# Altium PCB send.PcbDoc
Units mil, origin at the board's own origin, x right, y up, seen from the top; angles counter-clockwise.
Board outline 1102.36 x 1608 mil, 2 copper layers (Top Layer, Bottom Layer); 45 components, 38 nets, 165 pads, 231 vias.
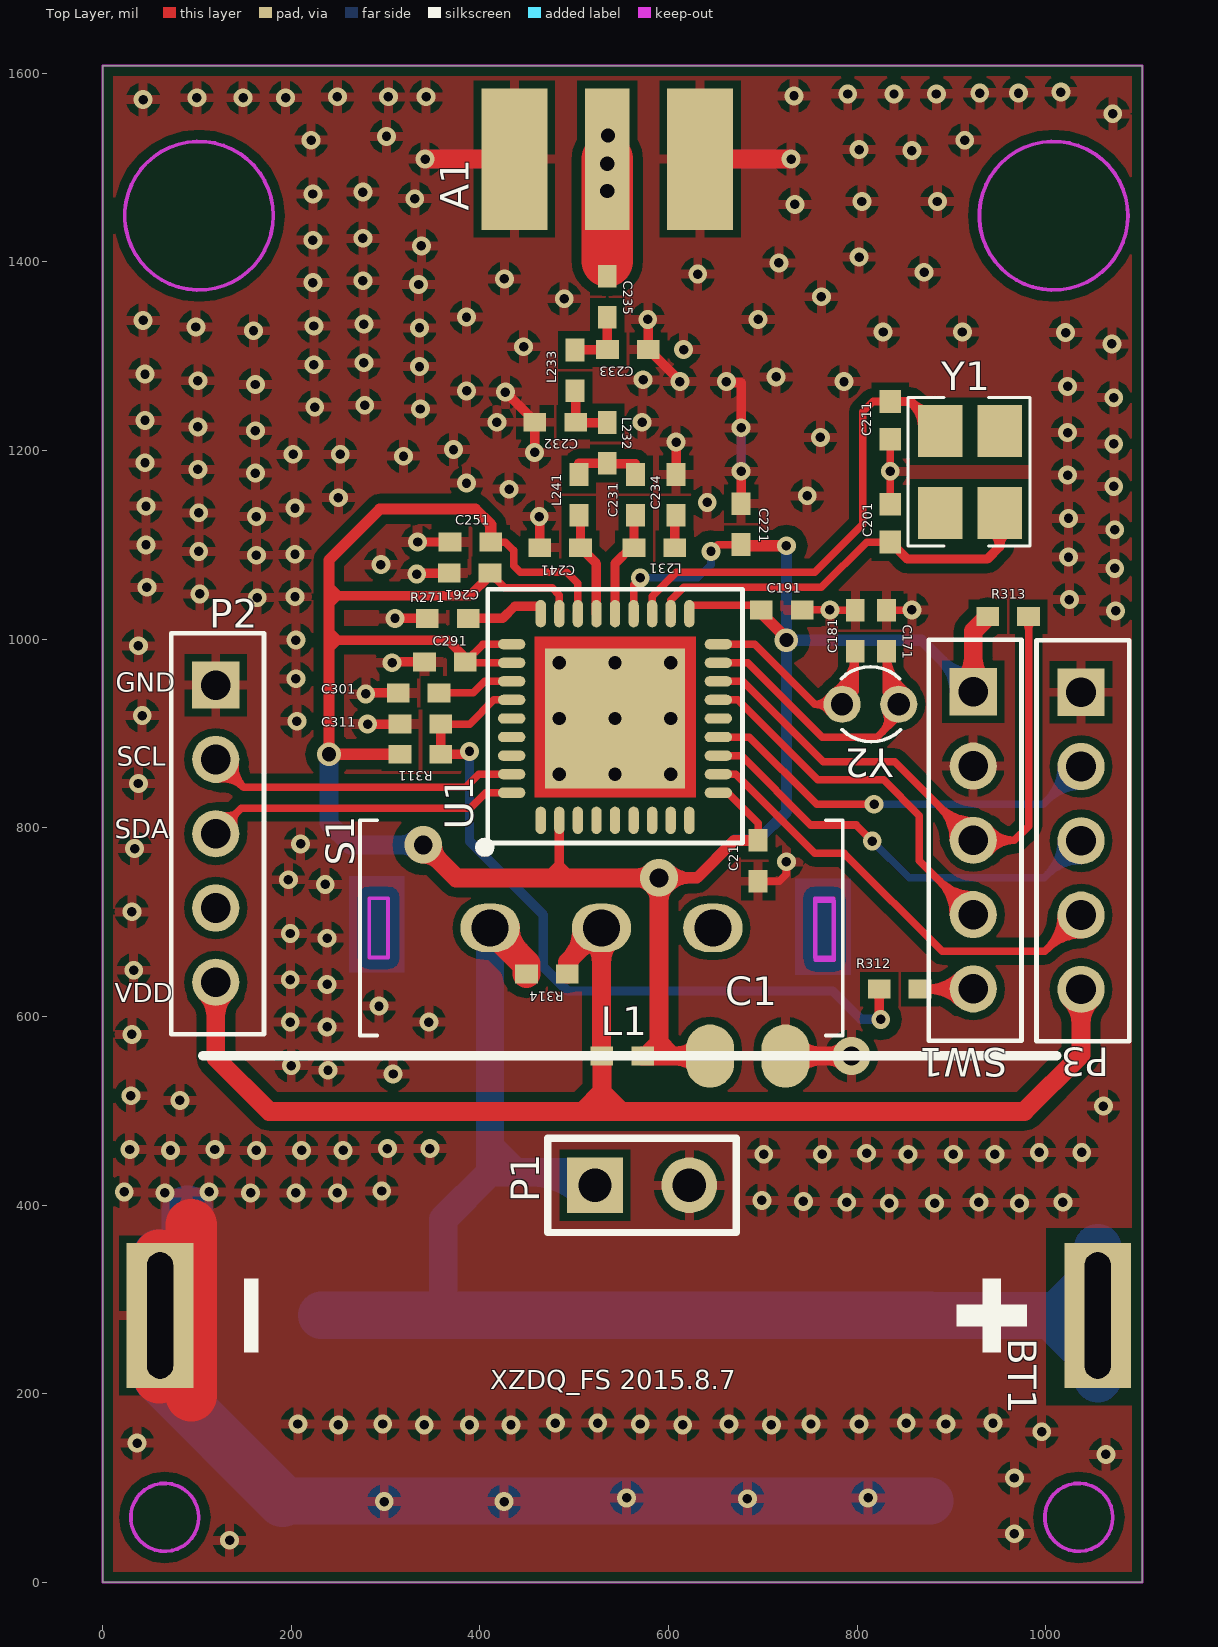
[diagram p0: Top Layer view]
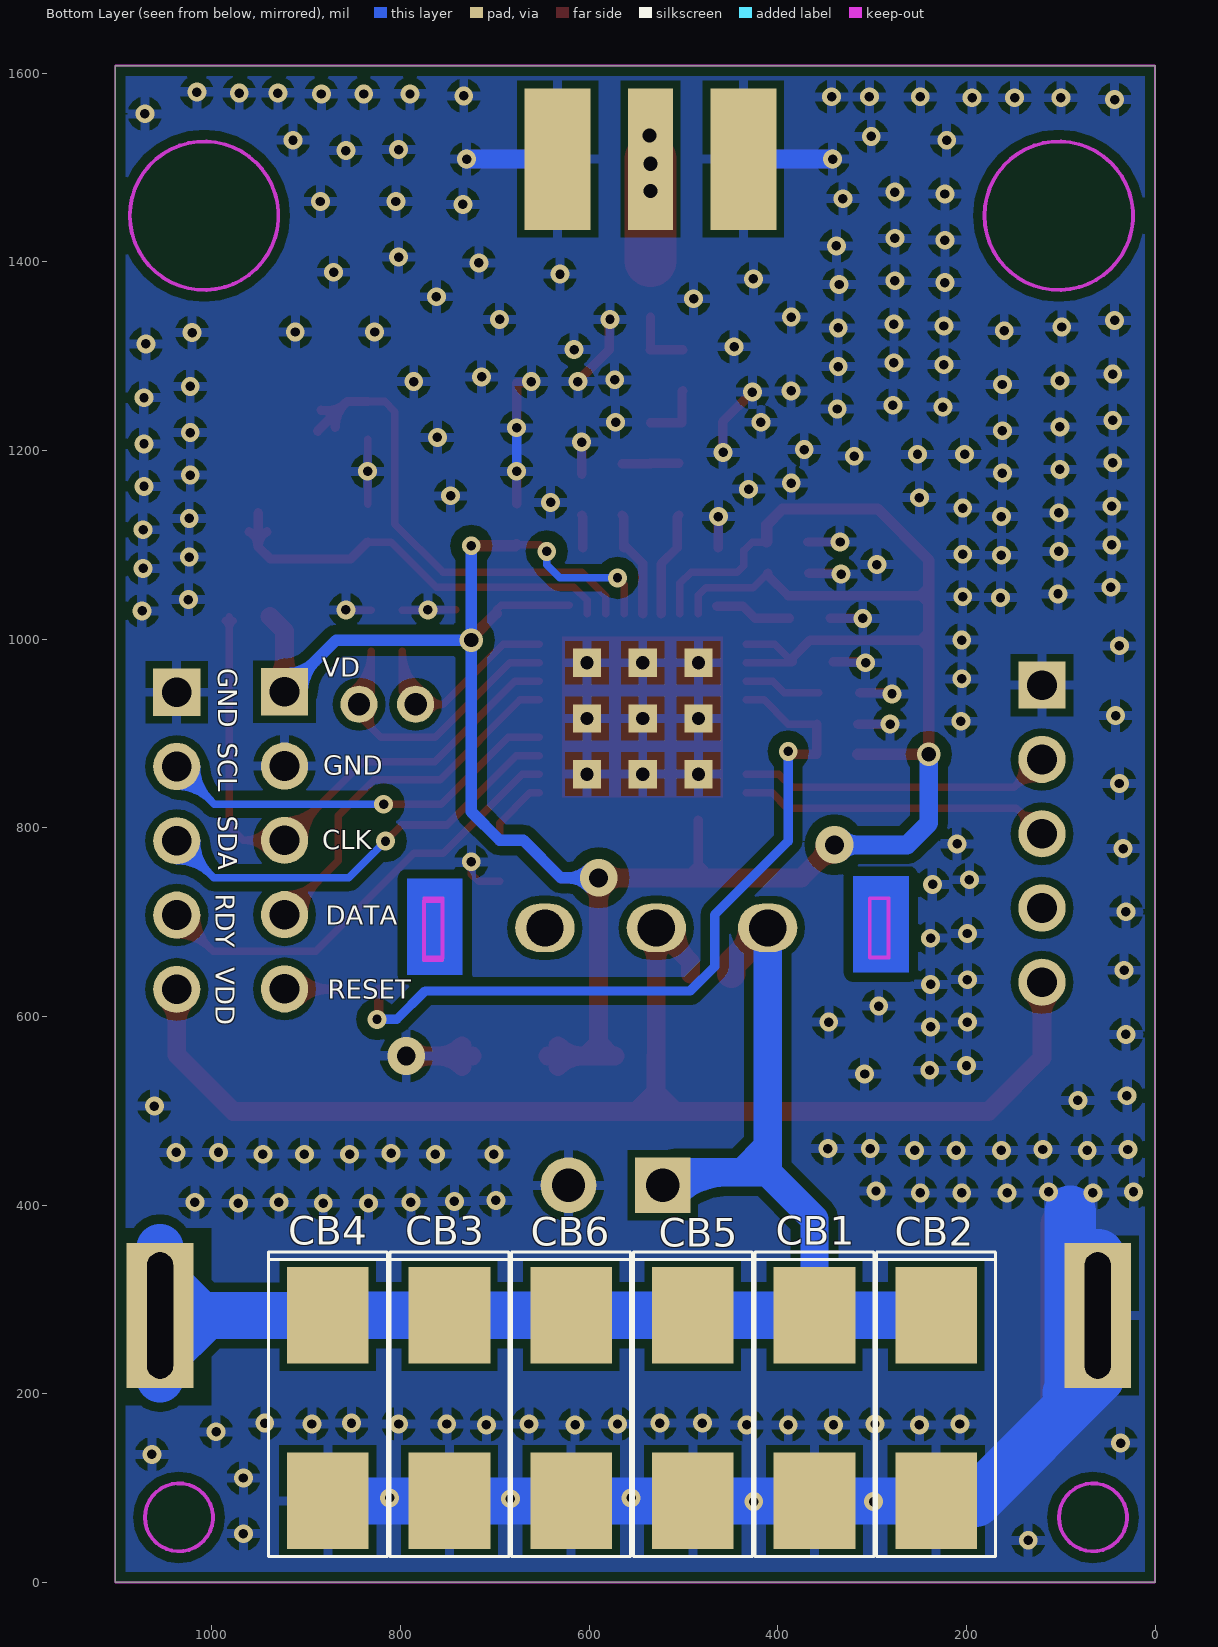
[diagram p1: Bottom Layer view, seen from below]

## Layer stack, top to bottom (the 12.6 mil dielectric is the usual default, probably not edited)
Top Layer: signal copper 1.4
Dielectric: dielectric 12.6, FR-4, Dk 4.8
Bottom Layer: signal copper 1.4

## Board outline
0,0 0,1608 1102.36,1608 1102.36,0

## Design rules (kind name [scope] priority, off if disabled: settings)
Clearance FILLTOPAD [ISFILL vs ISPAD] p1: gap=9
Clearance InPolygon_GND [InNamedPolygon('GND') vs InNet('GND')] p2: gap=8
Clearance InPolygon_GND_P2 [InNamedPolygon('GND_P2') vs InNet('GND')] p3: gap=8
Clearance "InPolygon_GND layer1" [InNamedPolygon('GND layer1') vs InNet('GND')] p4: gap=8
Clearance InPolygon_GND_P1 [InNamedPolygon('GND_P1') vs InNet('GND')] p5: gap=8
Clearance CopperToBoard [InPolygon vs (IsTrack Or IsArc) And OnLayer('Keep-out Layer')] p6: gap=10
Clearance ViaToCopper [IsVia vs InPolygon] p7: gap=12
Clearance ViaToVia [IsVia vs IsVia] p8: gap=8
Clearance PadToCopper [IsPad vs InPolygon] p9: gap=8
Clearance PadToVia [ISPad vs IsVia] p10: gap=8
Clearance PadToPad [IsPad vs IsPad] p11: gap=8
Clearance RouteToPad_1 [IsTrack or IsArc vs IsVia] p12: gap=8
Clearance RouteToPad [IsTrack Or IsArc vs IsPad] p13: gap=8
Clearance RouteToRoute [IsTrack or IsArc vs IsTrack or IsArc] p14: gap=8
Clearance [All] p15: gap=10
ComponentClearance [All] p1: gap=0 collisioncheckmode=3 verticalgap=0 showdistances=FALSE
HoleSize [All] p1: absolutevalues=TRUE maxlimit=1000 minlimit=1 maxpercent=80.000 minpercent=20.000
MinimumSolderMaskSliver [All] p1: minsoldermaskwidth=0
PolygonConnect [All] p1: connectstyle=Relief reliefconductorwidth=10 reliefentries=4 polygonreliefangle="90 Angle"
RoutingVias [All] p1: holewidth=28 width=50 viastyle="Through Hole" minholewidth=10 minwidth=20 maxholewidth=28 maxwidth=50
SilkToSilkClearance [All] p1: silktosilkclearance=0
SilkscreenOverComponentPads [All] p1: minsilkscreentomaskgap=0
SolderMaskExpansion [All] p1: expansion=4
Width [All] p1: maxlimit=60 minlimit=8 preferedwidth=10
23 further rules are at their usual default settings.

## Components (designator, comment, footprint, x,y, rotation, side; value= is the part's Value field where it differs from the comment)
A1 "Antenna" SMA_AT 533.94,1507.93 r180 top
BT1 "VBAT3.6V" BAT 1054.94,283.93 r180 top
C1 "2U2" "0805 (reflow)" 683.94,556.93 r0 top
C21 "100nF" "0402 (REFLOW)" 694.94,764.93 r270 top
C171 "CAP" "0402 (REFLOW)" 830.94,1008.93 r90 top
C181 "CAP" "0402 (REFLOW)" 797.94,1008.93 r90 top
C191 "220pF" "0402 (REFLOW)" 719.94,1030.93 r0 top
C201 "CAP" "0402 (REFLOW LF)" 833.94,1122.93 r90 top
C211 "CAP" "0402 (REFLOW LF)" 835.94,1231.93 r270 top
C221 "100nF" "0402 (REFLOW)" 676.94,1121.93 r90 top
C231 "3.9pF" "0402 (REFLOW)" 564.94,1152.93 r90 top
C232 "8.2pF" "0402 (REFLOW)" 479.94,1229.93 r180 top
C233 "5.6pF" "0402 (REFLOW)" 556.94,1306.93 r0 top
C234 "220pF" "0402 (REFLOW)" 607.94,1152.93 r90 top
C235 "220pF" "0402 (REFLOW)" 534.94,1362.93 r90 top
C241 "3.9pF" "0402 (REFLOW)" 484.94,1096.93 r180 top
C251 "100nF" "0402 (REFLOW)" 389.94,1102.93 r180 top
C261 "220pF" "0402 (REFLOW)" 388.94,1069.93 r180 top
C291 "100nF" "0402 (REFLOW)" 362.94,975.93 r180 top
C301 "1uF" "0402 (REFLOW)" 334.94,942.93 r0 top
C311 "1nF" "0402 (REFLOW)" 336.94,909.93 r180 top
CB1 "220uF" 6032C 359.06,183.81 r90 bottom
CB2 "220uF" 6032C 230.07,183.81 r90 bottom
CB3 "220uF" 6032C 746.04,183.81 r90 bottom
CB4 "220uF" 6032C 875.03,183.81 r90 bottom
CB5 "220uF" 6032C 488.05,183.81 r90 bottom
CB6 "220uF" 6032C 617.04,183.81 r90 bottom
L1 "BLM15HG102SN1D" "0402 (REFLOW)" 550.94,557.93 r180 top
L231 "27nH" "0402 (REFLOW)" 584.94,1096.93 r0 top
L232 "22nH" "0402 (REFLOW)" 534.94,1207.93 r90 top
L233 "27nH" "0402 (REFLOW)" 500.94,1284.93 r90 top
L241 "27nH" "0402 (REFLOW)" 504.94,1152.93 r90 top
P1 "Header 2" HDR1X2 521.94,420.93 r0 top
P2 "Header 5" HD5 119.94,636.23 r90 top
P3 "Header 5" HD5 1037.25,628.7 r90 top
R271 "56K" "0402 (REFLOW)" 365.94,1021.93 r0 top
R311 "2.7K" "0402 (REFLOW)" 336.94,877.93 r180 top
R312 "2.7K" "0402 (REFLOW)" 844.94,628.93 r0 top
R313 "10K" "0402 (REFLOW)" 959.94,1023.93 r180 top
R314 "0R" "0402 (REFLOW)" 470.94,644.93 r0 top
S1 "SS-12F24" SS-12F24 527.83,693.93 r0 top
SW1 "Header 5" HD5 922.94,629.19 r90 top
U1 "CC1110" QLP36/QFN/CC1110 543.2,916.43 r90 top
Y1 "XY1" "XTAL_SMD_3_2x2_5 (3.2 x 2.5 mm)" 948.93,1134.93 r90 top
Y2 "XTAL" "CJ32.768K 2MM*6MM" 783.94,930.93 r0 top

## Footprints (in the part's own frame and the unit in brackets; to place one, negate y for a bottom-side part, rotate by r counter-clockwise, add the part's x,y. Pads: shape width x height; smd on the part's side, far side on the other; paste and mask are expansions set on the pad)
"0402 (REFLOW LF)" [mil]
  rect 24x23 smd paste+0 mask+6: 1(-20,-1) 2(20,-1)
"0402 (REFLOW)" [mil]
  rect 24x20 smd paste+0 mask+4: 1(-21.65,0) 2(21.65,0)
"0805 (reflow)" [mil]
  oval 51x67 smd paste+0 mask+4: 1(-40,1) 2(40,1)
6032C [mm]
  rect 2.6x2.2 smd: 1(2.525,0.051) 2(-2.475,0.051)
  silkscreen extent -3.97,-1.55 4.23,1.65
BAT [mm]
  rect 1.8x3.9 hole 0.7 slot 3.4 at 90 deg: 1(0,0.025) 2(25.25,0.025)
  silkscreen extent 1.1,-6.97 24.1,1.03
"CJ32.768K 2MM*6MM" [mm]
  round 1 hole 0.6: 1(0,0) 2(1.524,0)
  silkscreen extent -0.03,-1.01 1.57,1.01
HD5 [mm]
  round 1.27 hole 0.8 mask+0.07: 1(0,0) 2(2,0) 3(4,0) 4(6,0)
  rect 1.27x1.27 hole 0.8 mask+0.07: 5(8,0)
  silkscreen extent -1.4,-1.3 9.4,1.2
HDR1X2 [mm] "Connector; Header; 2 Position"
  rect 1.5x1.5 hole 0.9: 1(0,0)
  round 1.5 hole 0.9: 2(2.54,0)
  silkscreen extent -1.27,-1.27 3.81,1.27
QLP36/QFN/CC1110 [mil]
  oval 29x11 smd paste-2 mask+4: 1(-108.5,78.74) 2(-108.5,59.06) 3(-108.5,39.37) 4(-108.5,19.68) 5(-108.5,0) 6(-108.5,-19.69) 7(-108.5,-39.37) 8(-108.5,-59.06) 9(-108.5,-78.74) 19(110.5,-78.74) 20(110.5,-59.06) 21(110.5,-39.37) 22(110.5,-19.69) 23(110.5,0) 24(110.5,19.68) 25(110.5,39.37) 26(110.5,59.06) 27(110.5,78.74)
  oval 11x29 smd paste-2 mask+4: 10(-79.32,-109.5) 11(-59.63,-109.5) 12(-39.94,-109.5) 13(-20.26,-109.5) 14(-0.57,-109.5) 15(19.11,-109.5) 16(38.8,-109.5) 17(58.48,-109.5) 18(78.17,-109.5) 28(78.17,109.5) 29(58.48,109.5) 30(38.8,109.5) 31(19.11,109.5) 32(-0.57,109.5) 33(-20.26,109.5) 34(-39.94,109.5) 35(-59.63,109.5) 36(-79.32,109.5)
  rect 30x30 / inner round 60 / far side rect 30x30 hole 14 paste+0 mask+0: 37(-59.63,59.06) 39(-0.57,59.06) 41(58.48,59.06) 47(-59.63,0) 49(-0.57,0) 51(58.48,0) 57(-59.63,-59.06) 59(-0.57,-59.06) 61(58.48,-59.06)
  rect 30x30 smd mask+0: 38(-30.1,59.06) 40(28.95,59.06) 42(-59.63,29.53) 43(-30.1,29.53) 44(-0.57,29.53) 45(28.95,29.53) 46(58.48,29.53) 48(-30.1,0) 50(28.95,0) 52(-59.63,-29.53) 53(-30.1,-29.53) 54(-0.57,-29.53) 55(28.95,-29.53) 56(58.48,-29.53) 58(-30.1,-59.06) 60(28.95,-59.06)
  silkscreen extent -147,-135 136,148
SMA_AT [mil]
  rect 47.24x150 smd far side: 1(-1,-1)
  rect 47.24x150 smd: 1(-1,-1)
  rect 70x150 smd: 2(-99.43,-1) 3(97.43,-1)
  rect 70x150 smd far side: 4(-99.43,-1) 5(97.43,-1)
SS-12F24 [mm]
  oval 1.6x1.3 hole 1: 1(-2.975,0) 2(0.025,0) 3(3.025,0)
  Bottom Layer region: -6.775,-1.2 -5.275,-1.2 -5.275,1.4 -6.775,1.4
  Bottom Layer region: 5.24,-1.276 6.74,-1.276 6.74,1.324 5.24,1.324
  Keep-Out Layer lines w0.1: -6.225,-0.8 -5.725,-0.8 -5.725,0.8 -6.225,0.8 -6.225,0 -6.225,-0.8 ; 5.775,-0.8 5.775,0 5.775,0.8 6.275,0.8 6.275,-0.8 5.775,-0.8 ; 5.79,-0.876 5.79,-0.076 5.79,0.724 6.29,0.724 6.29,-0.876 5.79,-0.876
  silkscreen extent -6.47,-2.9 6.53,2.9
"XTAL_SMD_3_2x2_5 (3.2 x 2.5 mm)" [mm]
  rect 1.4x1.2 smd paste-0.06 mask+0.05: 1(-0.025,-0.051) 2(2.175,-0.051) 3(2.175,1.549) 4(-0.025,1.549)
  silkscreen extent -0.93,-0.86 3.07,2.41

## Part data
BT1: library part Battery, "Multicell Battery"
C1 C21 C191 C221 C231 C232 C233 C234 C235 C241 C251 C261 C291 C301 C311: library part CAP, "CAP"
CB1 CB2 CB3 CB4 CB5 CB6: library part CAP+
L1 L231 L232 L233 L241: library part Inductor, "Inductor"
P1: "Header, 2-Pin"
P2 P3 SW1: "Header, 5-Pin"
R271 R311 R312 R313 R314: library part RES, "RES"
S1: library part SW-SPDT, "Switch"
U1: "Single chip transceiver"
Y1: "四脚晶振"
Y2: "晶振"

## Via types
v1: diameter 20, hole 10, Top Layer to Bottom Layer, 217 vias
v2: diameter 20, hole 10, Top Layer to Bottom Layer, tented both sides, 5 vias
v3: diameter 30, hole 15, Top Layer to Bottom Layer, 3 vias
v4: diameter 40, hole 20, Top Layer to Bottom Layer, tented both sides, 3 vias
v5: diameter 25, hole 15, Top Layer to Bottom Layer, tented both sides, 2 vias
v6: diameter 20, hole 10, Top Layer to Bottom Layer, tented bottom, 1 vias

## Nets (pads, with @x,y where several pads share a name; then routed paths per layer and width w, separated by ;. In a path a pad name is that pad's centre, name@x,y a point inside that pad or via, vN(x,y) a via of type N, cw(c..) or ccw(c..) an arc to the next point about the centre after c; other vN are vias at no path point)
101: C201.1 U1.20 Y1.1 | length 475.8
  Top Layer w8: U1.20 602.25,1041 616.18,1054.93 761.94,1054.93 809.94,1102.93 C201.1
  Top Layer w10: C201.1 852.94,1084.93 937.94,1084.93 950.93,1097.92 ; Y1.1@941.7,1113.82 cw(c932.63,1097.92) 950.93,1097.92 ; Y1.1 950.93,1097.92 ; Y1.1@960.16,1113.82 ccw(c969.23,1097.92) 950.93,1097.92
276: C211.1 U1.21 Y1.3 | length 547.5
  Top Layer w8: U1.21 582.57,1045.56 607.94,1070.93 754.94,1070.93 805.94,1121.93 805.94,1240.93 816.94,1251.93 C211.1
  Top Layer w10: C211.1 856.55,1251.93 Y1.3 ; 858.52,1249.96 ccw(c877.81,1269.25) Y1.3@883.83,1242.64 ; 858.93,1249.55 cw(c833.86,1224.48) Y1.3@869.31,1224.48
489: C181.1 U1.18 Y2.1 | length 380.2
  Top Layer w8: U1.18 691.27,994.6 754.94,930.93 ; Y2.1@770.81,922.34 ccw(c754.94,911.97) 754.94,930.93 ; Y2.1@770.81,939.51 cw(c754.94,949.89) 754.94,930.93 ; Y2.1@775.07,943.87 ccw(c745.31,987.27) C181.1 797.94,944.93 Y2.1 754.94,930.93 ; Y2.1@779.59,937.27 ccw(c755.72,972.09) 797.94,972.09 ; Y2.1@784.12,930.67 ccw(c766.13,956.9) 797.94,956.9
490: C171.1 U1.17 Y2.2 | length 470.1
  Top Layer w8: U1.17 683.95,974.91 762.94,895.93 820.94,895.93 843.94,918.93 Y2.2 830.94,943.93 C171.1 ccw(c884.93,987.27) Y2.2@853.16,943.61 ; 826.94,901.93 ccw(c814.01,914.86) Y2.2@830.12,923.51 ; 830.94,955.85 ccw(c862.06,955.85) Y2.2@843.75,930.67 ; 830.94,971.56 ccw(c873.5,971.56) Y2.2@848.46,937.14 ; 834.55,909.54 ccw(c823.91,920.18) Y2.2@837.17,927.29
531: C301.2 U1.30 | length 82.2
  Top Layer w8: C301.2 392.94,942.93 405.24,955.23 U1.30
536: R271.2 U1.27 | length 82.7
  Top Layer w10: R271.2 423.94,1021.93 436.94,1034.93 U1.27@464.94,1034.93
561: C1.1 C21.1 C191.1 C221.1 C251.1 C261.1 C291.1 L1.1 R311.2 R313.2 SW1.5 U1.2 U1.10 U1.19 U1.22 U1.25 U1.26 U1.28 U1.29 | length 3865
  Top Layer w8: C261.1 426.08,1054.44 476.43,1054.44 484.14,1046.72 U1.26 ; C251.1 426.94,1102.93 435.94,1093.93 435.94,1077.93 442.94,1070.93 491.94,1070.93 503.83,1059.04 U1.25 ; U1.29 385.61,974.91 C291.1 403.26,994.6 U1.28 ; U1.22 562.88,1057.87 v1(569.94,1064.93) ; U1.19@620.94,1035.93 693.28,1035.93 C191.1 C191.1@698.28,1027.58 ; v1(644.94,1092.93) 652.28,1100.28 C221.1 ; U1.10 662.75,837.12 694.94,804.93 C21.1 ; v5(724.94,998.93) v5@724.94,1000.93
  Top Layer w10: 239.94,989.93 248.94,998.93 ; 239.94,998.93 252.94,998.93 ; 239.94,1007.93 248.94,998.93 ; 239.94,1036.93 248.94,1045.93 254.94,1045.93 ; 239.94,1045.93 254.94,1045.93 ; 239.94,1055.93 249.94,1045.93 254.94,1045.93 ; C291.1 384.59,980.28 365.94,998.93 252.94,998.93 ; C261.1 410.59,1067.58 388.94,1045.93 254.94,1045.93 ; 469.94,746.93 484.14,761.13 484.14,763.93 ; U1.2 484.14,763.93 ; 484.94,746.93 484.14,747.72 484.14,763.93 ; 497.94,746.93 484.14,760.72 484.14,763.93 ; 248.94,998.93 252.94,998.93 ; 248.94,998.93 252.94,998.93
  Top Layer w12: R311.2 v5(239.94,877.93) 239.94,1083.93 293.94,1137.93 394.94,1137.93 411.59,1121.28 C251.1 ; v4(589.94,746.93) 629.94,746.93 669.59,786.58 C21.1 ; v4@599.84,737.03 cw(c623.74,713.13) 623.74,746.93 cw(c623.74,780.73) v4@599.84,756.83 ; C221.1 678.28,1098.93 v2(724.94,1098.93) ; C191.1@698.28,1027.58 v5@724.94,1000.93
  Top Layer w20: v4@339.94,771.93 cw(c339.94,747.79) 357.01,764.86 cw(c374.08,781.93) v4@349.94,781.93 ; v4(339.94,781.93) 374.94,746.93 v4(589.94,746.93) 589.94,579.93 ; L1.1 C1.1 ; L1.1@576.94,558.93 589.94,571.93 ; v4@582.87,754 cw(c565.79,771.07) 565.79,746.93 cw(c565.79,722.79) 582.87,739.86 cw(c565.79,722.79) 589.94,722.79 cw(c614.08,722.79) v4@597.01,739.86 ; 589.94,557.93 589.94,579.93 ; 601.94,559.93 589.94,571.93 ; C1.1@632.98,546.97 ccw(c606.52,520.51) 606.52,557.93 ccw(c606.52,595.35) C1.1@632.98,568.89 ; SW1.5@912.33,954.76 ccw(c886.72,980.36) 922.94,980.36 ccw(c959.15,980.36) SW1.5@933.54,954.76 ; SW1.5 922.94,1008.58 R313.2 ; 589.94,571.93 589.94,579.93
  Bottom Layer w8: v1(569.94,1064.93) 630.94,1064.93 644.94,1078.93 v1(644.94,1092.93)
  Bottom Layer w12: v4(589.94,746.93) 629.94,746.93 669.94,786.93 694.94,786.93 724.94,816.93 v5(724.94,998.93) ; v4@599.84,737.03 cw(c623.74,713.13) 623.74,746.93 cw(c623.74,780.73) v4@599.84,756.83 ; v2(724.94,1098.93) v5(724.94,998.93) ; SW1.5@903.94,944.15 ccw(c858.07,944.15) 890.5,976.58 ccw(c922.94,1009.02) SW1.5@922.94,963.15 ; SW1.5 868.16,998.93 v5(724.94,998.93)
  Bottom Layer w20: v5(239.94,877.93) 239.94,804.93 262.94,781.93 v4(339.94,781.93) ; v4@332.87,774.86 ccw(c315.79,757.79) 315.79,781.93 ccw(c315.79,806.07) v4@332.87,789
564: C233.1 C235.1 L233.2 | length 69
  Top Layer w10: L233.2 534.94,1306.58 C233.1 534.94,1307.28 C235.1
565: C232.1 L232.2 L233.1 | length 67.1
  Top Layer w10: L233.1 501.59,1262.62 C232.1 501.94,1229.58 L232.2
567: C231.2 L232.1 L241.2 | length 60
  Top Layer w10: L241.2@504.94,1186.28 L232.1 ; L232.1@534.94,1185.93 C231.2@564.94,1185.93
568: C234.1 L231.2 | length 34.9
  Top Layer w10: L231.2 606.59,1129.93 C234.1
569: C231.1 L231.1 U1.23 | length 113.4
  Top Layer w10: U1.23 543.2,1080.19 L231.1@560.94,1097.93 ; L231.1 563.28,1129.62 C231.1
570: C241.1 L241.1 U1.24 | length 112
  Top Layer w10: L241.1 506.59,1129.62 C241.1 523.51,1080.01 U1.24
571: A1.1 C235.2 | length 108
  Top Layer w55: 534.94,1400.93 A1.1@534.94,1508.93
  other v3: 534.94,1474.93 534.94,1503.93 535.94,1533.93
584: C311.1 R311.1 R312.1 U1.31 | length 842.5
  Top Layer w8: C311.1 388.94,909.93 414.55,935.54 U1.31
  Top Layer w10: C311.1 R311.1 385.94,877.93 v2(388.94,880.93) ; R312.1@819.75,625.39 cw(c811.21,616.86) 823.28,616.86 cw(c835.35,616.86) R312.1@826.82,625.39 ; R312.1 823.28,598.58 v2(824.94,596.93)
  Bottom Layer w10: v2(388.94,880.93) 388.94,785.93 466.94,707.93 466.94,652.93 492.94,626.93 773.94,626.93 803.94,596.93 v2(824.94,596.93)
DEBUG_CLOCK: R313.1 SW1.3 U1.16 | length 880.5
  Top Layer w8: U1.16 678.64,955.23 763.94,869.93 839.68,869.93 SW1.3 966.68,786.67 ; SW1.3@901.94,786.67 ccw(c851.24,786.67) 887.09,822.52 ccw(c922.94,858.37) SW1.3@922.94,807.67 ; SW1.3@909.94,786.67 ccw(c878.55,786.67) 900.74,808.86 ccw(c922.94,831.05) SW1.3@922.94,799.67 ; SW1.3@933.08,778.54 cw(c950.01,764.97) 950.01,786.67 cw(c950.01,808.37) SW1.3@933.08,794.8 ; SW1.3@939.32,773.54 cw(c966.68,751.62) 966.68,786.67 ; SW1.3@939.32,799.8 ccw(c966.68,821.72) 966.68,786.67 ; R313.1@977.35,1019.69 cw(c967.11,1009.44) 981.59,1009.44 cw(c996.08,1009.44) R313.1@985.83,1019.69 ; R313.1 981.59,801.58 966.68,786.67
DEBUG_DATA: SW1.2 U1.15 | length 521.6
  Top Layer w8: U1.15 673.32,935.54 757.94,850.93 827.94,850.93 865.94,812.93 865.94,764.93 SW1.2 ; SW1.2@901.94,707.93 ccw(c851.24,707.93) 887.09,743.78 ccw(c922.94,779.63) SW1.2@922.94,728.93 ; SW1.2@909.94,707.93 ccw(c878.55,707.93) 900.74,730.12 ccw(c922.94,752.31) SW1.2@922.94,720.93
DRDYN: P3.2 U1.11 | length 607.3
  Top Layer w8: U1.11 671.06,856.8 754.94,772.93 785.94,772.93 889.94,668.93 998.74,668.93 P3.2 ; P3.2@1016.25,707.44 cw(c965.55,707.44) 1001.4,671.59 cw(c1037.25,635.74) P3.2@1037.25,686.44 ; P3.2@1024.25,707.44 cw(c992.87,707.44) 1015.06,685.25 cw(c1037.25,663.06) P3.2@1037.25,694.44
GND: A1.2 A1.3 A1.4 A1.5 BT1.2 C1.2 C21.2 C171.2 C181.2 C191.2 C201.2 C211.2 C221.2 C232.2 C233.2 C234.2 C241.2 C251.2 C261.2 C291.2 C301.1 C311.2 CB1.2 CB2.2 CB3.2 CB4.2 CB5.2 CB6.2 P1.2 P2.5 P3.5 R271.1 SW1.4 U1.37 U1.38 U1.39 U1.40 U1.41 U1.42 U1.43 U1.44 U1.45 U1.46 U1.47 U1.48 U1.49 U1.50 U1.51 U1.52 U1.53 U1.54 U1.55 U1.56 U1.57 U1.58 U1.59 U1.60 U1.61 | length 2829
  Top Layer w8: C21.2 717.28,743.28 724.94,750.93 v1(724.94,763.93) ; C191.2 v1(770.94,1030.93) 771.28,1030.58 C181.2 ; C171.2 857.59,1030.58 v1(857.94,1030.93) ; C201.2 v1(834.94,1177.93) C211.2
  Top Layer w10: v1(278.94,941.93) 279.94,942.93 C301.1 ; v1(280.94,909.93) C311.2 ; v1(306.94,974.93) 307.94,975.93 C291.2 ; v1(309.94,1021.93) R271.1 ; v1(332.94,1068.93) 333.94,1069.93 C261.2 ; v1(333.94,1102.93) C251.2 ; v1(426.94,1261.93) 458.28,1230.58 C232.2 458.28,1198.28 v1(457.94,1197.93) ; v1(462.94,1129.93) 463.28,1129.58 C241.2 ; v1(577.94,1338.93) 578.59,1338.28 C233.2 611.94,1273.58 v1(611.94,1272.93) ; C234.2 v1(607.94,1208.93) ; v1(661.34,1272.93) 662.34,1271.93 676.94,1271.93 v1(676.94,1224.03) ; C221.2 v1(676.94,1177.93)
  Top Layer w20: v1(341.94,1508.93) A1.3 ; A1.2 v1(729.94,1508.93) ; C1.2 v4(793.94,557.93) ; C1.2@734.9,546.97 cw(c761.36,520.51) 761.36,557.93 cw(c761.36,595.35) C1.2@734.9,568.89 ; v4@786.87,550.86 ccw(c769.79,533.79) 769.79,557.93 ccw(c769.79,582.07) v4@786.87,565
  Top Layer w55: BT1.2@60,217 BT1.2@60,346.87 ; 94,198 94,379
  Bottom Layer w10: v1(676.94,1177.93) v1(676.94,1224.03)
  Bottom Layer w20: v1(341.94,1508.93) A1.5 ; A1.4 v1(729.94,1508.93)
  Bottom Layer w50: CB2.2@190.48,86.38 CB2.2 CB4.2
  Bottom Layer w55: BT1.2@59.94,346.93 59.94,216.93 CB2.2@190.48,86.38 ; 90,393 90,203 92,201
  other v1: 134.54,44.63 298.54,85.63 425.54,85.63 683.54,88.63 555.54,89.63 811.54,89.63 966.54,110.63 1063.54,135.63 36.54,147.63 995.54,159.63 249.94,166.93 340.94,166.93 388.94,166.93 432.94,166.93 614.94,166.93 708.94,166.93 206.94,167.93 296.94,167.93 569.94,167.93 663.94,167.93 750.94,167.93 801.94,167.93 893.94,167.93 479.94,168.93 524.94,168.93 851.94,168.93 943.94,168.93 833.94,401.93 881.94,401.93 971.94,401.93 788.94,402.93 928.94,402.93 1017.94,402.93 742.94,403.93 698.94,404.93 65.94,412.93 156.94,412.93 204.94,412.93 248.94,412.93 22.94,413.93 112.94,413.93 295.94,414.93 700.94,453.93 762.94,453.93 853.94,453.93 901.94,453.93 945.94,453.93 809.94,454.93 992.94,455.93 1037.94,455.93 71.94,457.93 162.94,457.93 210.94,457.93 254.94,457.93 28.94,458.93 118.94,458.93 301.94,459.93 346.94,459.93 1060.94,504.93 81.94,510.93 29.94,515.93 307.94,538.93 238.94,542.93 199.94,547.93 30.94,580.93 237.94,588.93 198.94,593.93 345.94,593.93 293,610.93 237.94,633.93 198.94,638.93 32.94,648.93 237.94,682.93 198.94,687.93 30.94,710.93 235.94,739.93 196.94,744.93 33.94,777.93 209.94,782.93 37.94,846.93 205.94,912.93 41.94,918.93 204.94,957.93 37.94,992.93 204.94,998.93 1073.94,1029.93 1024.94,1041.93 163.94,1043.93 203.94,1044.93 102.94,1047.93 46.94,1054.93 1072.94,1074.93 294.94,1078.93 1023.94,1086.93 162.94,1088.93 203.94,1089.93 101.94,1092.93 45.94,1099.93 1072.94,1115.93 1023.94,1127.93 162.94,1129.93 101.94,1133.93 203.94,1138.93 45.94,1140.93 640.94,1144.93 249.94,1149.93 746.94,1151.93 430.94,1158.93 1071.94,1161.93 385.74,1165.33 1022.94,1173.93 161.94,1175.93 100.94,1179.93 44.94,1186.93 318.94,1193.93 201.94,1195.93 251.94,1195.93 371.94,1200.93 1071.94,1206.93 760.94,1213.93 1022.94,1218.93 161.94,1220.93 100.94,1224.93 417.94,1229.93 571.97,1229.93 44.94,1231.93 336.94,1243.93 224.94,1245.93 277.94,1247.93 1071.94,1255.93 385.94,1263.13 1022.94,1267.93 161.94,1269.93 785.94,1272.93 100.94,1273.93 572.94,1274.93 714.01,1277.93 44.94,1280.93 335.94,1288.93 223.94,1290.93 276.94,1292.93 615.94,1306.93 446.34,1309.93 1069.94,1312.93 1020.94,1324.93 827.44,1325.63 911.54,1325.63 159.94,1326.93 335.94,1329.93 98.94,1330.93 223.94,1331.93 276.94,1333.93 42.94,1337.93 694.94,1338.93 385.74,1341.33 489.34,1360.83 761.94,1362.93 334.94,1375.93 222.94,1377.93 275.94,1379.93 425.94,1381.93 630.94,1386.93 870.94,1388.93 716.94,1398.93 801.94,1404.93 337.94,1416.93 222.94,1422.93 275.94,1424.93 733.94,1460.93 804.94,1463.93 884.94,1463.93 330.94,1466.93 222.94,1471.93 275.94,1473.93 857.94,1517.93 801.94,1518.93 220.94,1528.93 913.94,1528.93 300.94,1532.93 1070.94,1556.93 42.94,1571.93 99.94,1573.93 148.94,1573.93 193.94,1573.93 248.94,1574.93 302.94,1574.93 342.94,1574.93 732.94,1575.93 789.94,1577.93 838.94,1577.93 883.94,1577.93 929.94,1578.93 970.94,1578.93 1015.94,1579.93
  other v6: 966.54,51.63
HDC_SCL: P3.4 U1.13 | length 559.6
  Top Layer w8: U1.13 685.69,896.17 756.94,824.93 v2(817.94,824.93)
  Bottom Layer w8: v2(817.94,824.93) 997.26,824.93 P3.4 ; P3.4@1016.25,864.92 cw(c965.55,864.92) 1001.4,829.07 cw(c1037.25,793.22) P3.4@1037.25,843.92 ; P3.4@1024.25,864.92 cw(c992.87,864.92) 1015.06,842.73 cw(c1037.25,820.54) P3.4@1037.25,851.92
HDC_SDA: P3.3 U1.12 | length 583.4
  Top Layer w8: U1.12 677.38,876.49 750.94,802.93 798.94,802.93 v2(815.94,785.93)
  Bottom Layer w8: v2(815.94,785.93) 854.94,746.93 998,746.93 P3.3 ; P3.3@1016.25,786.18 cw(c965.55,786.18) 1001.4,750.33 cw(c1037.25,714.48) P3.3@1037.25,765.18 ; P3.3@1024.25,786.18 cw(c992.87,786.18) 1015.06,763.99 cw(c1037.25,741.8) P3.3@1037.25,773.18
NetR312_2: R312.2 SW1.1 | length 132.3
  Top Layer w10: R312.2 922.68,628.93 SW1.1 ; R312.2@874.03,628.93 ccw(c874.03,678.1) SW1.1@908.79,643.33 ; R312.2@875.28,628.93 cw(c875.28,581.53) SW1.1@908.79,615.05
P0_0: U1.5
P0_1: U1.6
P0_2: U1.7
P0_3: U1.8
P0_4: U1.9
P1_0: U1.4
P1_1: U1.3
P1_2: U1.1
P1_5: U1.34
P1_6: U1.33
P1_7: U1.32
P2_0: U1.14
TMP_SCL: P2.4 U1.35 | length 425.3
  Top Layer w8: P2.4 149.46,842.93 ; P2.4@121.84,859.59 cw(c124.64,840.61) 138.21,854.18 cw(c151.78,867.74) P2.4@132.8,870.55 ; P2.4@123.01,851.67 cw(c127.54,821.01) 149.46,842.93 ; P2.4@140.71,869.38 ccw(c171.37,864.85) 149.46,842.93 ; U1.35 398.81,856.8 384.94,842.93 149.46,842.93
TMP_SDA: P2.3 U1.36 | length 373.3
  Top Layer w8: P2.3 142.05,815.82 ; P2.3@119.94,812.93 135.07,812.93 ccw(c135.07,822.8) 142.05,815.82 ; P2.3@138.94,797.93 138.94,808.31 cw(c149.56,808.31) 142.05,815.82 ; U1.36 406.13,837.12 389.94,820.93 147.16,820.93 142.05,815.82
VBAT+: BT1.1 CB1.1 CB2.1 CB3.1 CB4.1 CB5.1 CB6.1 P1.1 R314.1 S1.1 | length 1863.1
  Top Layer w30: S1.1 449.28,655.36 R314.1 ; S1.1@427.21,693.93 ccw(c467.04,693.93) 438.88,665.77
  Bottom Layer w30: CB1.1 361.06,385.05 410.72,434.71 ; S1.1 410.72,461.93 ; 444.94,434.71 437.94,434.71 410.72,461.93 ; 453.6,434.71 cw(c453.6,352.59) P1.1@511.66,410.66 ; P1.1 508.16,434.71 410.72,434.71 ; 410.72,434.71 410.72,461.93
  Bottom Layer w50: CB2.1 CB4.1 877.33,282.93 1006,282.93 ; BT1.1@1054,325 1011.93,282.93 1006,282.93 ; BT1.1@1054.94,215.93 BT1.1@1054.94,354.93 ; BT1.1 1006,282.93 ; BT1.1@1055,222 1055,233.93 1006,282.93
VDD: L1.2 P2.1 P3.1 R314.2 S1.2 | length 1660.6
  Top Layer w20: P2.1@109.33,625.62 cw(c83.72,600.02) 119.94,600.02 cw(c156.15,600.02) P2.1@130.54,625.62 ; P2.1 119.94,555.93 176.59,499.28 529.28,499.28 ; R314.2 492.59,657.69 S1.2 528.83,558.39 L1.2 529.28,519.93 ; 495.54,660.65 ccw(c466.67,689.52) S1.2@507.38,692.71 ; 506.39,671.49 cw(c522.92,654.96) S1.2@522.92,678.34 ; 509.94,499.28 509.94,500.58 529.28,519.93 ; S1.2@517.8,682.91 cw(c491.19,656.29) 528.83,656.29 cw(c566.47,656.29) S1.2@539.85,682.91 ; 551.94,499.28 549.94,499.28 529.28,519.93 ; P3.1@1026.65,618.09 cw(c1001.04,592.49) 1037.25,592.49 cw(c1073.47,592.49) P3.1@1047.86,618.09 ; P3.1 1037.25,559.24 977.28,499.28 529.28,499.28 ; 529.28,499.28 529.28,519.93
pads on no net: P2.2 S1.3 Y1.2 Y1.4

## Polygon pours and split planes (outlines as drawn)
GND on Top Layer "GND layer1" (solid, remove dead copper, pour order 1000): 0,1608 1102.36,1608 1102.36,0 0,0 0,1608
GND on Bottom Layer "GND" (solid, remove dead copper, pour order 1001): 0,1608 1102.36,1608 1102.36,0 0,0 0,1608

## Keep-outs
Keep-Out Layer:
  circle w4: c1034.87,68.93 r36.07
  circle w4: c65.87,68.93 r36.07
  circle w4: c1008.17,1448.93 r78.77
  circle w4: c102.17,1448.93 r78.77
  lines w2: 0,0 0,1608 1102.36,1608 1102.36,0 0,0

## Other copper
Top Layer:
  rectangle net GND: 457.94,831.93 628.94,1002.93
  pour cut-out: 1102.36,376 1000,376 1000,187 1102.36,187
  pour cut-out: 449.94,1008.93 634.94,1008.93 634.94,823.93 449.94,823.93
Bottom Layer:
  pour cut-out: 1102.36,376 1000,376 1000,187 1102.36,187

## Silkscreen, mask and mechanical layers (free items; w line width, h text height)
Top Overlay:
  text "GND" at 14,944 h20
  text "SCL" at 15,866 h20
  text "SDA" at 13,789 h20
  text "VDD" at 13,615 h20
  text "XZDQ_FS 2015.8.7" at 411,205 h20
Bottom Overlay:
  text "GND" at 993,969 h20 r90
  text "VD" at 883,960 h20
  text "SCL" at 993,890 h20 r90
  text "GND" at 882,856 h20
  text "SDA" at 993,813 h20 r90
  text "CLK" at 883,777 h20
  text "RDY" at 996,730 h20 r90
  text "DATA" at 879,697 h20
  text "VDD" at 996,652 h20 r90
  text "RESET" at 877,619 h20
